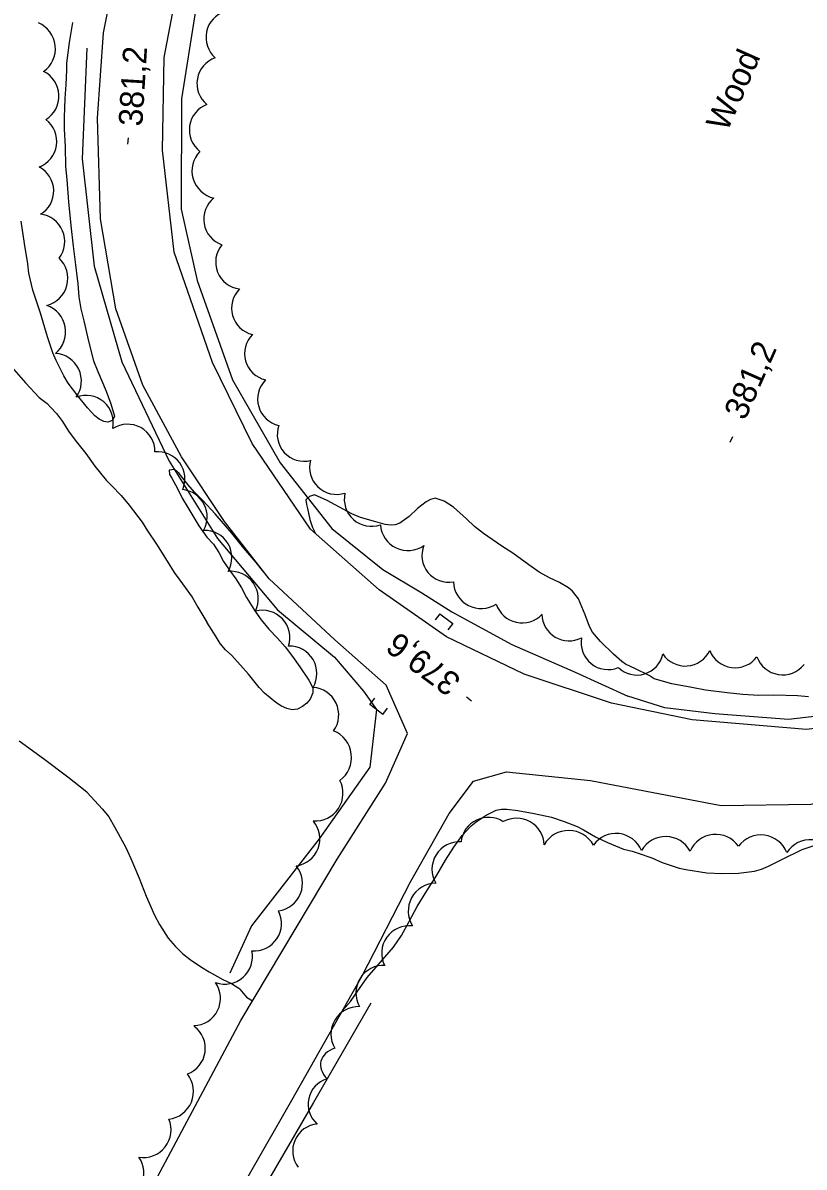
# Model space of a CAD drawing. Extents: x 287698 to 290158, y 5234163 to 5237182.
# Drawn here: x 288819.3 to 288917.4, y 5235919.8 to 5236063.6 of the extents above; entities that cross this region are included whole.
import ezdxf

# ---------------------------------------------------------------- set-up
doc = ezdxf.new("R2010")
doc.units = 0
for name, color, linetype in [('Niveau 1', 7, 'Continuous'), ('Niveau 2', 7, 'Continuous'), ('Niveau 21', 7, 'Continuous'), ('Niveau 26', 7, 'Continuous'), ('Niveau 3', 7, 'Continuous'), ('Niveau 4', 7, 'Continuous'), ('Niveau 44', 7, 'Continuous')]:
    doc.layers.add(name, color=color, linetype=linetype)

msp = doc.modelspace()

# ---------------------------------------------------------------- linework, layer by layer
at = {"layer": 'Niveau 1'}
for points in [[(288817.87, 5236020.38), (288819.64, 5236018.38), (288821.34, 5236016.5), (288822.37, 5236015.75), (288822.76, 5236015.29), (288823.52, 5236014.51), (288824.27, 5236013.51), (288825.05, 5236012.3), (288825.89, 5236011.14), (288827.19, 5236009.48), (288828.36, 5236007.9), (288829.78, 5236006.12), (288830.44, 5236005.46), (288831.63, 5236004.19), (288832.64, 5236002.97), (288834.28, 5236000.85), (288834.95, 5235999.75), (288836.07, 5235998.07), (288837.44, 5235995.96), (288838.32, 5235994.51), (288839.02, 5235993.56), (288840.57, 5235991.44), (288841.28, 5235990.18), (288842.39, 5235988.3)], [(288848.6, 5235995.79), (288847.06, 5235997.58), (288845.54, 5235999.45), (288843.44, 5236001.91), (288841.91, 5236003.57), (288840.86, 5236004.63), (288840.03, 5236005.58), (288838.94, 5236006.98), (288838.33, 5236007.47), (288837.66, 5236007.4), (288837.7, 5236006.86), (288838.02, 5236006.37), (288838.74, 5236005.09), (288839.32, 5236003.88), (288840.01, 5236002.7), (288841.4, 5236000.39), (288842.42, 5235998.95), (288843.23, 5235998.1), (288843.9, 5235997.06), (288844.52, 5235995.9), (288845.25, 5235994.81), (288846.06, 5235993.73), (288846.78, 5235992.61), (288847.41, 5235991.4), (288848.42, 5235989.69), (288849.25, 5235988.58), (288850.21, 5235987.42), (288851.27, 5235986.29), (288852.23, 5235985.18), (288853.18, 5235983.96), (288854.09, 5235982.69), (288855.22, 5235981), (288855.72, 5235980.03), (288855.72, 5235979.41), (288855.41, 5235978.61), (288854.99, 5235978.12), (288854.42, 5235977.67), (288853.8, 5235977.36), (288853.14, 5235977.28), (288852.48, 5235977.44), (288851.78, 5235977.74), (288851.07, 5235978.17), (288849.65, 5235979.35), (288848.98, 5235980.07), (288847.65, 5235981.73), (288845.55, 5235984.09), (288844.75, 5235984.8), (288844.1, 5235985.59), (288843.6, 5235986.43), (288842.39, 5235988.3)], [(288917.99, 5235978.92), (288916.59, 5235979.02), (288913.65, 5235979.12), (288911.74, 5235979.09), (288909.76, 5235979.18), (288907.79, 5235979.41), (288905.04, 5235979.75), (288903.33, 5235980.06), (288900.84, 5235980.52), (288898.59, 5235981.17), (288897.96, 5235981.59), (288896.28, 5235982.44), (288895.02, 5235983), (288894.54, 5235983.36), (288893.51, 5235984.26), (288891.85, 5235985.84), (288890.87, 5235987.04), (288890.5, 5235987.73), (288889.94, 5235989.22), (288889.08, 5235991.2), (288888.33, 5235992.2), (288887.84, 5235992.61), (288886.72, 5235993.25), (288885.45, 5235993.87), (288884.14, 5235994.59), (288882.85, 5235995.48), (288880.83, 5235996.94), (288879.48, 5235997.85), (288877.16, 5235999.41), (288876.05, 5236000.31), (288875.02, 5236001.28), (288873.41, 5236002.72), (288872.23, 5236003.5), (288871.1, 5236003.86), (288870.5, 5236003.71), (288869.98, 5236003.41), (288868.88, 5236002.56), (288867.82, 5236001.56), (288866.67, 5236000.73), (288866.07, 5236000.5), (288865.48, 5236000.47), (288864.83, 5236000.57), (288863.63, 5236000.89), (288861.72, 5236001.46), (288860.64, 5236001.88), (288860.06, 5236002.21), (288857.54, 5236003.59), (288855.92, 5236004.29), (288855.29, 5236004.08), (288854.86, 5236003.65), (288854.92, 5236003.06), (288855.07, 5236002.56), (288855.36, 5236001.2), (288855.67, 5236000.18), (288856.06, 5235999.44)], [(288849.59, 5235994.58), (288848.6, 5235995.79)]]:
    msp.add_lwpolyline(points, dxfattribs=at)
at = {"layer": 'Niveau 2'}
for points in [[(288825.54, 5236063.63), (288825.1, 5236061.14), (288824.77, 5236058.54), (288824.77, 5236057.65), (288824.7, 5236055.86), (288824.58, 5236054.08), (288824.48, 5236051.69), (288824.49, 5236050.24), (288824.6, 5236048.08), (288824.67, 5236045.57), (288824.83, 5236043.9), (288825.04, 5236041.11), (288825.33, 5236038.12), (288825.6, 5236035.56), (288825.92, 5236033.2), (288826.2, 5236030.8), (288826.34, 5236029.16), (288826.6, 5236027.65), (288826.97, 5236026.15), (288827.53, 5236023.58), (288828.16, 5236021.13), (288828.71, 5236019.79), (288829.77, 5236017.32), (288830.34, 5236015.73), (288830.81, 5236014.16), (288830.55, 5236013.61), (288829.97, 5236013.44), (288829.46, 5236013.52), (288828.88, 5236013.79), (288828.34, 5236014.21), (288827.41, 5236015.21), (288826.19, 5236016.71), (288824.99, 5236018.34), (288824.45, 5236019.24), (288823.48, 5236021.15), (288823.08, 5236022.12), (288822.39, 5236024.13), (288821.51, 5236027.12), (288820.56, 5236030.03), (288820.07, 5236032.13), (288819.92, 5236033.32), (288819.51, 5236035.86), (288819.1, 5236038.7)], [(288827.33, 5235966.93), (288824.95, 5235968.79), (288821.89, 5235971.13), (288818.84, 5235973.33)], [(288827.33, 5235966.93), (288829.32, 5235964.79), (288830.11, 5235963.81), (288830.82, 5235962.57), (288832.24, 5235959.98), (288832.86, 5235958.59), (288833.93, 5235956.13), (288834.79, 5235953.87), (288835.84, 5235951.47), (288836.48, 5235950.31), (288837.55, 5235948.59), (288838.42, 5235947.56), (288839.37, 5235946.63), (288840.32, 5235945.91), (288841.75, 5235944.92), (288842.72, 5235944.34), (288844.44, 5235943.36), (288845.52, 5235942.86), (288846.45, 5235942.31), (288846.55, 5235942.16)], [(288859.46, 5235939.48), (288860.44, 5235940.6), (288860.99, 5235941.39), (288862.56, 5235943.63), (288863.68, 5235944.92), (288865.84, 5235947.45), (288866.87, 5235948.92), (288867.84, 5235950.65), (288868.85, 5235952.57), (288870.03, 5235954.52), (288871.29, 5235956.49), (288872.4, 5235958.38), (288873.45, 5235960.03), (288874.48, 5235961.48), (288875.6, 5235962.68), (288876.23, 5235963.18), (288877.49, 5235964.05), (288878.77, 5235964.67), (288879.41, 5235964.8), (288880.1, 5235964.8), (288881.47, 5235964.6), (288883.51, 5235964.24), (288885.69, 5235963.78), (288887.28, 5235963.25), (288888.94, 5235962.59), (288889.73, 5235962.17), (288891.24, 5235961.31), (288892.75, 5235960.6), (288894.76, 5235959.76), (288895.86, 5235959.52), (288896.58, 5235959.25), (288898.31, 5235958.66), (288899.62, 5235958.1), (288901.76, 5235957.35), (288902.59, 5235957.2), (288905.23, 5235956.78), (288907.12, 5235956.69), (288909.2, 5235956.76), (288911.2, 5235956.99), (288912.1, 5235957.26), (288912.95, 5235957.62), (288914.66, 5235958.45), (288917.21, 5235959.72), (288918.85, 5235960.27)], [(288846.55, 5235942.16), (288847.39, 5235941.16), (288848.14, 5235940.68)]]:
    msp.add_lwpolyline(points, dxfattribs=at)
at = {"layer": 'Niveau 21'}
for points in [[(288827.03, 5235900.87), (288836.55, 5235919.2), (288846.68, 5235938.23), (288858.78, 5235958.5), (288864.84, 5235968.06), (288867.6, 5235974.28), (288864.93, 5235980.35), (288858.47, 5235986.05), (288850.26, 5235993.73), (288844.63, 5236000.94), (288839.22, 5236009.08), (288834.37, 5236018.09), (288830.97, 5236027.65), (288829.04, 5236038.98), (288828.67, 5236051.62), (288829.41, 5236062.33), (288831.33, 5236071.9), (288834.49, 5236081.67)], [(288941.2, 5235979.75), (288929.47, 5235976.26), (288917.74, 5235974.79), (288903.38, 5235976.01), (288893.26, 5235978.11), (288882.29, 5235981.74), (288872.52, 5235986.46), (288864.07, 5235992.34), (288855.45, 5235999.98), (288848.12, 5236010.73), (288843.11, 5236020.91), (288838.3, 5236034.79), (288836.83, 5236047.62), (288837.06, 5236059.26), (288838.64, 5236067.62)], [(288842.78, 5235910.19), (288853.09, 5235928.23), (288861.92, 5235943.82), (288868.01, 5235955.64), (288872.86, 5235964.23), (288875.92, 5235968.3), (288880.07, 5235969.48), (288890.59, 5235968.37), (288907.02, 5235965.26), (288918.28, 5235965.41), (288928.58, 5235967.42), (288935.99, 5235968.05), (288942.64, 5235965.59), (288947.41, 5235961.56), (288953.07, 5235951.67), (288960.69, 5235934.21), (288968.41, 5235918.87)]]:
    msp.add_lwpolyline(points, dxfattribs=at)
at = {"layer": 'Niveau 26'}
for p, q in [((288871.7, 5235989.35), (288871.09, 5235988.56)), ((288871.7, 5235989.35), (288873.3, 5235988.12)), ((288873.3, 5235988.12), (288872.69, 5235987.33)), ((288862.9, 5235977.93), (288863.51, 5235978.72)), ((288864.5, 5235976.7), (288862.9, 5235977.93)), ((288864.5, 5235976.7), (288865.11, 5235977.49))]:
    msp.add_line(p, q, dxfattribs=at)
at = {"layer": 'Niveau 3'}
for p, q in [((288832.47, 5236048.36), (288832.55, 5236049.16)), ((288908.17, 5236010.89), (288908.49, 5236011.62)), ((288875.65, 5235978.37), (288875.01, 5235978.84))]:
    msp.add_line(p, q, dxfattribs=at)
at = {"layer": 'Niveau 4'}
for points in [[(288981.94, 5236072.28), (288984.83, 5236061.12), (288986.01, 5236047.01), (288985.36, 5236037.75), (288982.51, 5236023.63), (288976.44, 5236011.43), (288968.27, 5236000.99), (288959.32, 5235992.83), (288948.65, 5235985.02), (288939.53, 5235980.07), (288928.51, 5235977.58), (288915.46, 5235976.07), (288906.23, 5235976.75), (288899.96, 5235977.5), (288895.28, 5235979)], [(288841.59, 5236068.87), (288839.21, 5236054.06), (288839.18, 5236040.17), (288841.19, 5236031.21), (288845.63, 5236018.72), (288851.61, 5236008.3), (288858.12, 5236000.04), (288864.54, 5235994.9), (288869.4, 5235991.99), (288873.18, 5235989.58), (288880.74, 5235985.47), (288888.7, 5235982.02), (288895.28, 5235979)], [(288827.35, 5236060.44), (288826.73, 5236046.53), (288828.27, 5236033.04), (288831.72, 5236020.99), (288837.68, 5236008.53), (288843.77, 5235998.78), (288851.27, 5235989.82), (288858.45, 5235983.89), (288862.07, 5235979.61), (288863.71, 5235977.31), (288862.89, 5235970.05), (288856.52, 5235961.05), (288848.02, 5235950.13), (288845.31, 5235944.17)], [(288863.03, 5235940.4), (288855.81, 5235927.9), (288847.3, 5235913.29), (288839.7, 5235898.53), (288832.37, 5235884.38), (288824.13, 5235869.91), (288815.4, 5235854.66), (288809.83, 5235844.83), (288805.73, 5235838.52)]]:
    msp.add_lwpolyline(points, dxfattribs=at)
at = {"layer": 'Niveau 44'}
for centre, radius, start, end in [((288845.71, 5236061.77), 3.41, 107.1913, 228.7938), ((288821.42, 5236031.49), 3.52, 284.5435, 46.4343), ((288855.52, 5235976.64), 3.46, 324.3428, 85.9888), ((288887.87, 5235958.57), 3.54, 28.6793, 150.3936), ((288893.81, 5235958.24), 3.49, 22.8786, 144.4826), ((288900.04, 5235957.85), 3.49, 28.163, 149.9555), ((288906.33, 5235958.12), 3.5, 34.907, 156.7191), ((288912.02, 5235958.06), 3.49, 21.742, 143.7753), ((288918.22, 5235957.38), 3.56, 24.5188, 146.4436), ((288871.21, 5235951.98), 3.5, 90.7356, 212.3579), ((288861.48, 5235936.49), 3.48, 88.2459, 210.117)]:
    msp.add_arc(centre, radius, start, end, dxfattribs=at)
for centre, major_axis, ratio, start_param, end_param in [((288819.88, 5236060.37), (3.51, -0.17), 0.999835, 5.373438, 7.500789), ((288844.58, 5236055.98), (-3.36, 0.59), 0.999543, 5.219421, 7.341024), ((288820.37, 5236054.39), (-1.9, 2.9), 0.999995, 3.114444, 5.244157), ((288843.63, 5236050.15), (-3.38, 0.5), 0.998559, 5.220478, 7.341971), ((288820.11, 5236048.7), (3.41, -0.48), 0.998586, 5.215689, 7.344306), ((288844.05, 5236045.01), (3.42, -0.77), 0.999984, 2.594275, 4.718531), ((288819.77, 5236042.47), (-3.01, 1.59), 0.999983, 2.595203, 4.720026), ((288845.43, 5236038.93), (2.19, -2.61), 0.999995, 3.117231, 5.243321), ((288821.13, 5236036.14), (3.21, 1.23), 0.997657, 5.257527, 7.378997), ((288846.95, 5236033.56), (-3.18, -1.28), 0.999549, 5.217277, 7.344636), ((288848.93, 5236027.75), (2.46, -2.36), 0.999995, 3.118936, 5.244353), ((288821.16, 5236024.77), (3.46, 0.62), 0.99974, 5.220892, 7.345831), ((288850.56, 5236022.04), (-3.31, -0.79), 0.998053, 5.267071, 7.385305), ((288823.16, 5236018.58), (3.19, 1.42), 0.996755, 5.249682, 7.37016), ((288852.2, 5236016.34), (-3.27, -0.98), 0.997749, 5.214042, 7.340642), ((288827.23, 5236013.37), (-3.27, 1.07), 0.994244, 3.241928, 5.392261), ((288832.46, 5236009.74), (-3.01, 1.66), 0.995561, 3.636255, 5.788524), ((288854.65, 5236011.9), (-2.89, -1.79), 0.992519, 5.387246, 7.541306), ((288836.22, 5236006.31), (-3.38, 0.63), 0.989401, 2.915596, 4.99173), ((288858.71, 5236007.74), (-2.93, -1.73), 0.996386, 5.482249, 7.637391), ((288839.02, 5236001.54), (-3.11, 1.48), 0.993321, 3.06222, 5.055263), ((288863.1, 5236003.75), (-2.29, -2.55), 0.999727, 5.221616, 7.349071), ((288842.09, 5235996.37), (3.01, 1.73), 0.99384, 5.240966, 7.357782), ((288867.67, 5236000.75), (-1.67, -3.03), 0.998995, 5.284458, 7.405378), ((288872.8, 5235996.68), (-2.61, -2.14), 0.999856, 5.219295, 7.343281), ((288845.41, 5235991.21), (2.99, 1.76), 0.999275, 5.296001, 7.416855), ((288876.86, 5235993.46), (2.91, 1.89), 0.999984, 2.595542, 4.71878), ((288849.38, 5235986.32), (2.52, 2.38), 0.999733, 5.222482, 7.343591), ((288882.02, 5235991.59), (3.35, -0.62), 0.999612, 3.63418, 5.717622), ((288887.91, 5235989.35), (-0.43, -3.38), 0.998988, 4.862754, 6.885304), ((288852.78, 5235981.83), (3.15, 1.42), 0.999687, 5.331538, 7.457687), ((288892.82, 5235985.73), (-2.37, -2.45), 0.999488, 5.307031, 7.436843), ((288896.42, 5235984.99), (1, -3.2), 0.996646, 5.213927, 7.339408), ((288902.51, 5235986.16), (0.26, -3.38), 0.999307, 5.221598, 7.3449), ((288908.77, 5235985.98), (-0.47, -3.39), 0.99995, 5.220442, 7.350765), ((288914.75, 5235985.1), (-0.56, -3.39), 0.999994, 5.22127, 7.347292), ((288857, 5235971.29), (-3.32, 1.36), 0.999985, 2.590668, 4.720351), ((288856.03, 5235966.78), (2.74, -2.16), 0.999509, 5.310155, 7.432162), ((288877.78, 5235960.31), (-3.2, -1.3), 0.999263, 3.754782, 5.791501), ((288881.33, 5235960.18), (-3.12, 1.52), 0.999759, 3.635654, 5.67039), ((288853.14, 5235961.07), (3.24, -1.23), 0.999079, 5.219524, 7.344261), ((288874.15, 5235957.23), (-1.8, -2.95), 0.999457, 3.634419, 5.790359), ((288850.94, 5235955.44), (3.25, -1.26), 0.997383, 5.220469, 7.338346), ((288848.33, 5235950.44), (2.86, -1.97), 0.993112, 5.236158, 7.354464), ((288867.83, 5235946.68), (-2, -2.82), 0.999458, 3.634145, 5.790633), ((288844.65, 5235946.3), (2.29, -2.66), 0.992041, 5.232705, 7.345506), ((288864.6, 5235941.69), (-1.83, -2.94), 0.999455, 3.63638, 5.788398), ((288840.69, 5235941.03), (-1.83, 2.92), 0.997168, 2.609379, 4.761105), ((288838.79, 5235934.74), (-2.53, 2.33), 0.99396, 2.661125, 4.81987), ((288860.68, 5235932.14), (-3.93, 0.99), 0.669863, 5.466302, 7.100111), ((288837.22, 5235929.32), (3.25, -1.34), 0.999952, 5.221428, 7.345758), ((288858.57, 5235927.69), (-3.35, 0.75), 0.981088, 5.244564, 7.339741), ((288834.42, 5235924.5), (2.16, -2.75), 0.99993, 5.460991, 7.582539), ((288856.59, 5235921.83), (-3.1, 1.39), 0.998716, 5.223479, 7.345643), ((288831.12, 5235919.09), (3.03, -1.52), 0.995662, 5.249518, 7.36659)]:
    msp.add_ellipse(centre, major_axis=major_axis, ratio=ratio, start_param=start_param, end_param=end_param, dxfattribs=at)

# ---------------------------------------------------------------- texts
at = {"layer": 'Niveau 3'}
for s, rotation, p in [('381,2', 86.4772, (288834.3, 5236050.54)), ('381,2', 66.1217, (288910.01, 5236013.52)), ('379,6', 143.4682, (288874.52, 5235981.22))]:
    msp.add_text(s, height=3, rotation=rotation, dxfattribs=at).set_placement(p)
at = {"layer": 'Niveau 44'}
msp.add_text('Wood', height=3, rotation=66.1212, dxfattribs=at).set_placement((288907.77, 5236049.8))

doc.saveas('drawing.dxf')
